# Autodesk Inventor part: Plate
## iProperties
Created: 2002-01
Part Number: Plate
Document SubType Name: Modeling
Designer: ***
Control State: 0
Master: False
Checked Out: False
Shininess: 20.0
Length Units: 11269
Angle Units: 11279
Time Units: 11290
Mass Units: 11283
Length Display Precision: 3
Angle Display Precision: 2
Density: 0.0
Volumn: 0.0
Area: 0.0
PropertySet Name: Model Information
Author: ***
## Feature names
1. Extrusion1
